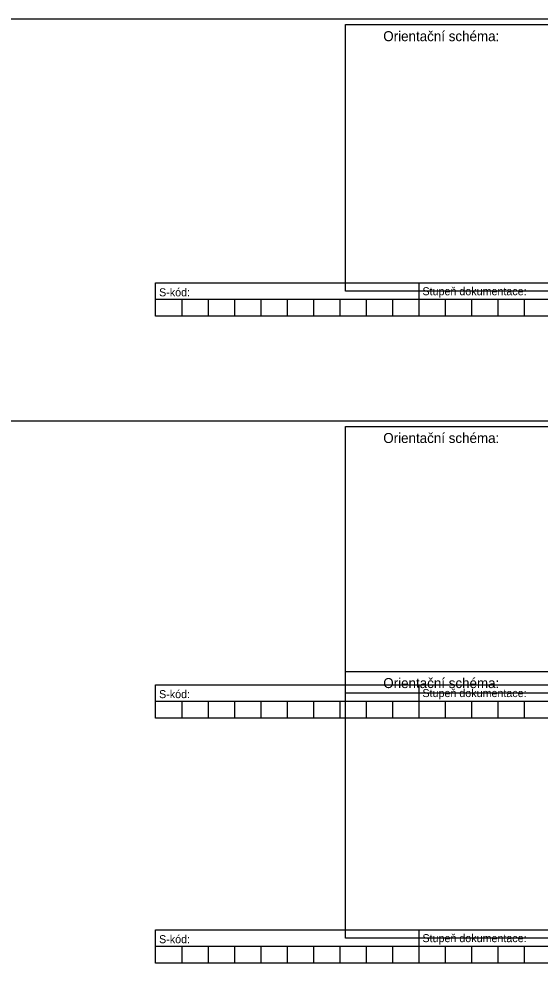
# Model space of a CAD drawing. Extents: x 1391 to 5528, y -6194 to 565.
# Drawn here: x 2976 to 3757, y -6194 to -4778 of the extents above; entities that cross this region are included whole.
import ezdxf

# ---------------------------------------------------------------- set-up
doc = ezdxf.new("R2010")
doc.units = 0
for name, color, linetype in [('Vrstva 11', 7, 'Continuous'), ('Vrstva 2', 7, 'Continuous'), ('Vrstva 8', 7, 'Continuous')]:
    doc.layers.add(name, color=color, linetype=linetype)

# ---------------------------------------------------------------- blocks, each defined once
blk = doc.blocks.new('_U1')
at = {"layer": 'Vrstva 8'}
for p, q in [((-4.55, 0.25), (-4.55, -0.25)), ((8.5, 0), (-8.5, 0)), ((-8.105, 0), (-8.105, -0.25)), ((-7.71, 0), (-7.71, -0.25)), ((-7.315, 0), (-7.315, -0.25)), ((-6.92, 0), (-6.92, -0.25)), ((-6.525, 0), (-6.525, -0.25)), ((-6.13, 0), (-6.13, -0.25)), ((-5.735, 0), (-5.735, -0.25)), ((-5.34, 0), (-5.34, -0.25)), ((-4.945, 0), (-4.945, -0.25)), ((-4.155, 0), (-4.155, -0.25)), ((-3.76, 0), (-3.76, -0.25)), ((-3.365, 0), (-3.365, -0.25)), ((-2.97, 0), (-2.97, -0.25))]:
    blk.add_line(p, q, dxfattribs=at)
blk.add_lwpolyline([(-8.5, 0.25), (8.5, 0.25), (8.5, -0.25), (-8.5, -0.25)], close=True, dxfattribs=at)
for s, p in [('S-kód:', (-8.445, 0.049)), ('Stupeň dokumentace:', (-4.497, 0.065))]:
    blk.add_text(s, height=0.12, dxfattribs=at).set_placement(p)
blk = doc.blocks.new('_U3')
at = {"layer": 'Vrstva 2'}
blk.add_lwpolyline([(-5.33255, 2.00005), (5.33245, 2.00005), (5.33245, -1.99995), (-5.33255, -1.99995)], close=True, dxfattribs=at)
blk.add_text('Orientační schéma:', height=0.15, dxfattribs=at).set_placement((-4.76755, 1.75005))

msp = doc.modelspace()

# ---------------------------------------------------------------- linework, layer by layer
at = {"layer": 'Vrstva 11'}
for p, q in [((1390.7, -4778), (5439, -4778)), ((1390.7, -5380.6), (5439, -5380.6))]:
    msp.add_line(p, q, dxfattribs=at)

# ---------------------------------------------------------------- block references
at = {"layer": 'Vrstva 2', "xscale": 100, "yscale": 100}
for p in [(3998.9, -4986.4), (3998.9, -5589), (3998.9, -5956.5)]:
    msp.add_blockref('_U3', p, dxfattribs=at)
at = {"layer": 'Vrstva 8', "xscale": 100, "yscale": 100}
for p in [(4030.6, -5198.9), (4030.6, -5801.5), (4030.6, -6169)]:
    msp.add_blockref('_U1', p, dxfattribs=at)

doc.saveas('drawing.dxf')
